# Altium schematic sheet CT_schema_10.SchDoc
size 278 x 170 mm
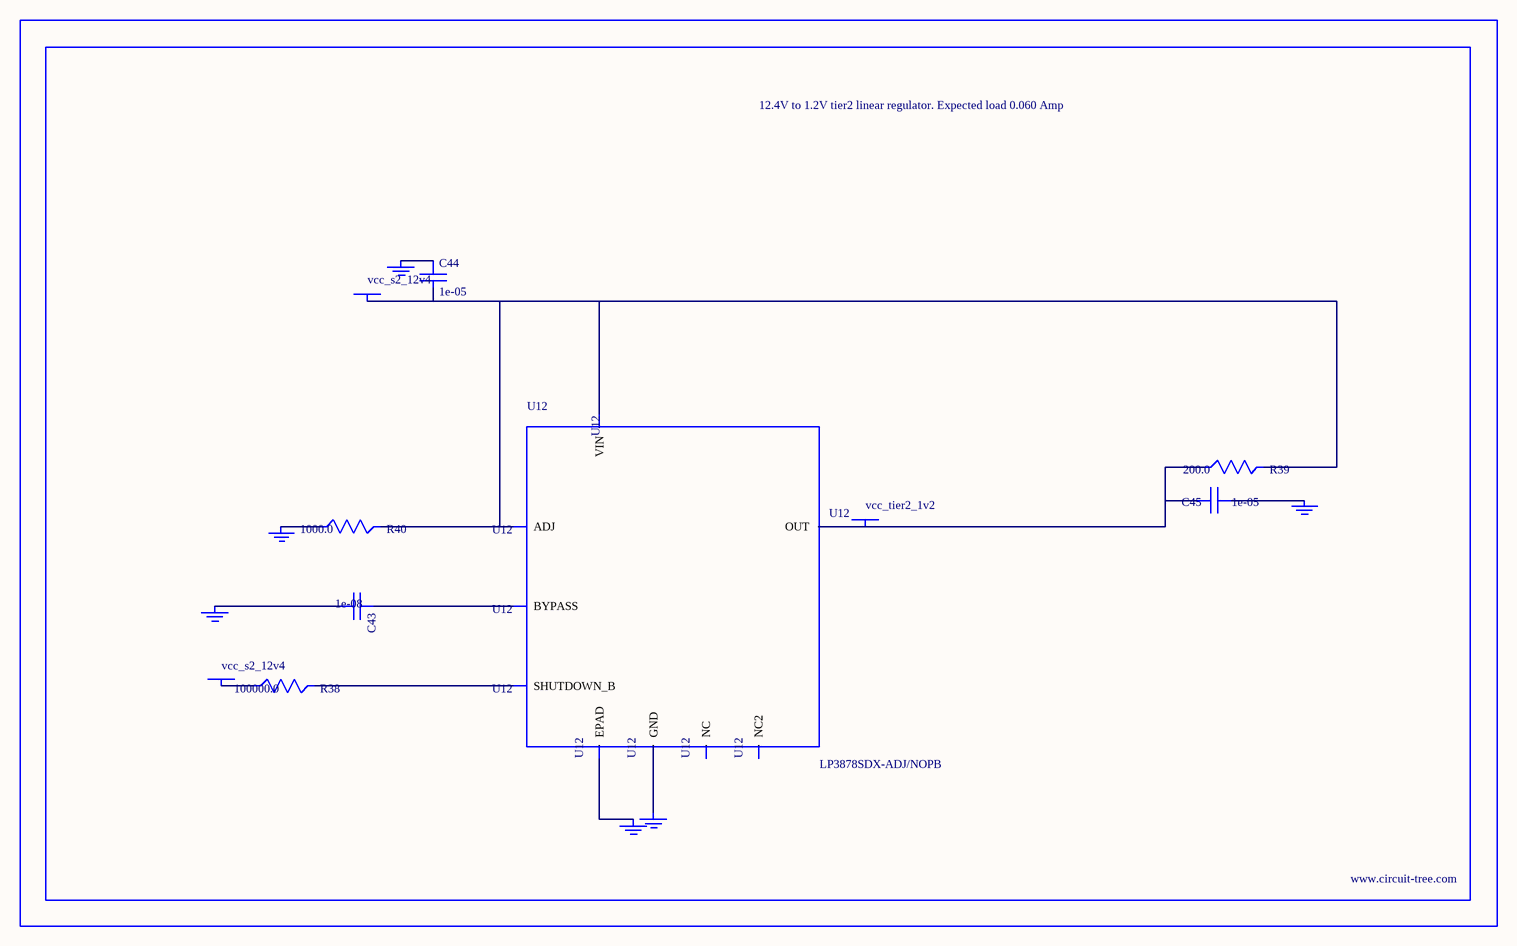
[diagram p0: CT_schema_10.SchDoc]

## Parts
BORDER9  (no value)
C43  1e-08  [C0402]
C44  1e-05  [C1210]
C45  1e-05  [C0805]
GND_INSTANCE_9_0  (no value)
GND_INSTANCE_9_1  (no value)
GND_INSTANCE_9_2  (no value)
GND_INSTANCE_9_3  (no value)
GND_INSTANCE_9_4  (no value)
GND_INSTANCE_9_5  (no value)
POWER_INSTANCE_9_0  vcc_s2_12v4
POWER_INSTANCE_9_1  vcc_s2_12v4
POWER_INSTANCE_9_2  vcc_tier2_1v2
R38  100000.0  [R0603]
R39  200.0  [R0603]
R40  1000.0  [R0603]
U12  LP3878SDX-ADJ/NOPB  [WSON-8]

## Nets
NetC43_1: C43.1 U12.1(BYPASS)
NetC43_2: C43.2 GND_INSTANCE_9_0.0(GND)
NetC44_1: C44.1 GND_INSTANCE_9_1.0(GND)
NetC44_2: C44.2 POWER_INSTANCE_9_0.0(PWR) R39.2 R40.2 U12.4(VIN) U12.6(ADJ)
NetC45_1: C45.1 GND_INSTANCE_9_2.0(GND)
NetC45_2: C45.2 POWER_INSTANCE_9_2.0(PWR) R39.1 U12.5(OUT)
NetGND_INSTANCE_9_3_0: GND_INSTANCE_9_3.0(GND) R40.1
NetGND_INSTANCE_9_4_0: GND_INSTANCE_9_4.0(GND) U12.PAD(EPAD)
NetGND_INSTANCE_9_5_0: GND_INSTANCE_9_5.0(GND) U12.3(GND)
NetPOWER_INSTANCE_9_1_0: POWER_INSTANCE_9_1.0(PWR) R38.1
NetR38_2: R38.2 U12.8(SHUTDOWN_B)

Not connected (* = marked no-connect by the designer): U12 2(NC) 7(NC2)

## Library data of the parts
BORDER9 = BORDER_PAGE9
C43 = C0402C103K3RAC
C44 = C1210C106K5PACTU
C45 = GRM219R60J106ME19D
GND_INSTANCE_9_0-GND_INSTANCE_9_5 = GND
POWER_INSTANCE_9_0-POWER_INSTANCE_9_2 = PWR
R38 = RC0603JR-07100KL
R39 = RC0603JR-07200RL
R40 = RC0603JR-071KL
